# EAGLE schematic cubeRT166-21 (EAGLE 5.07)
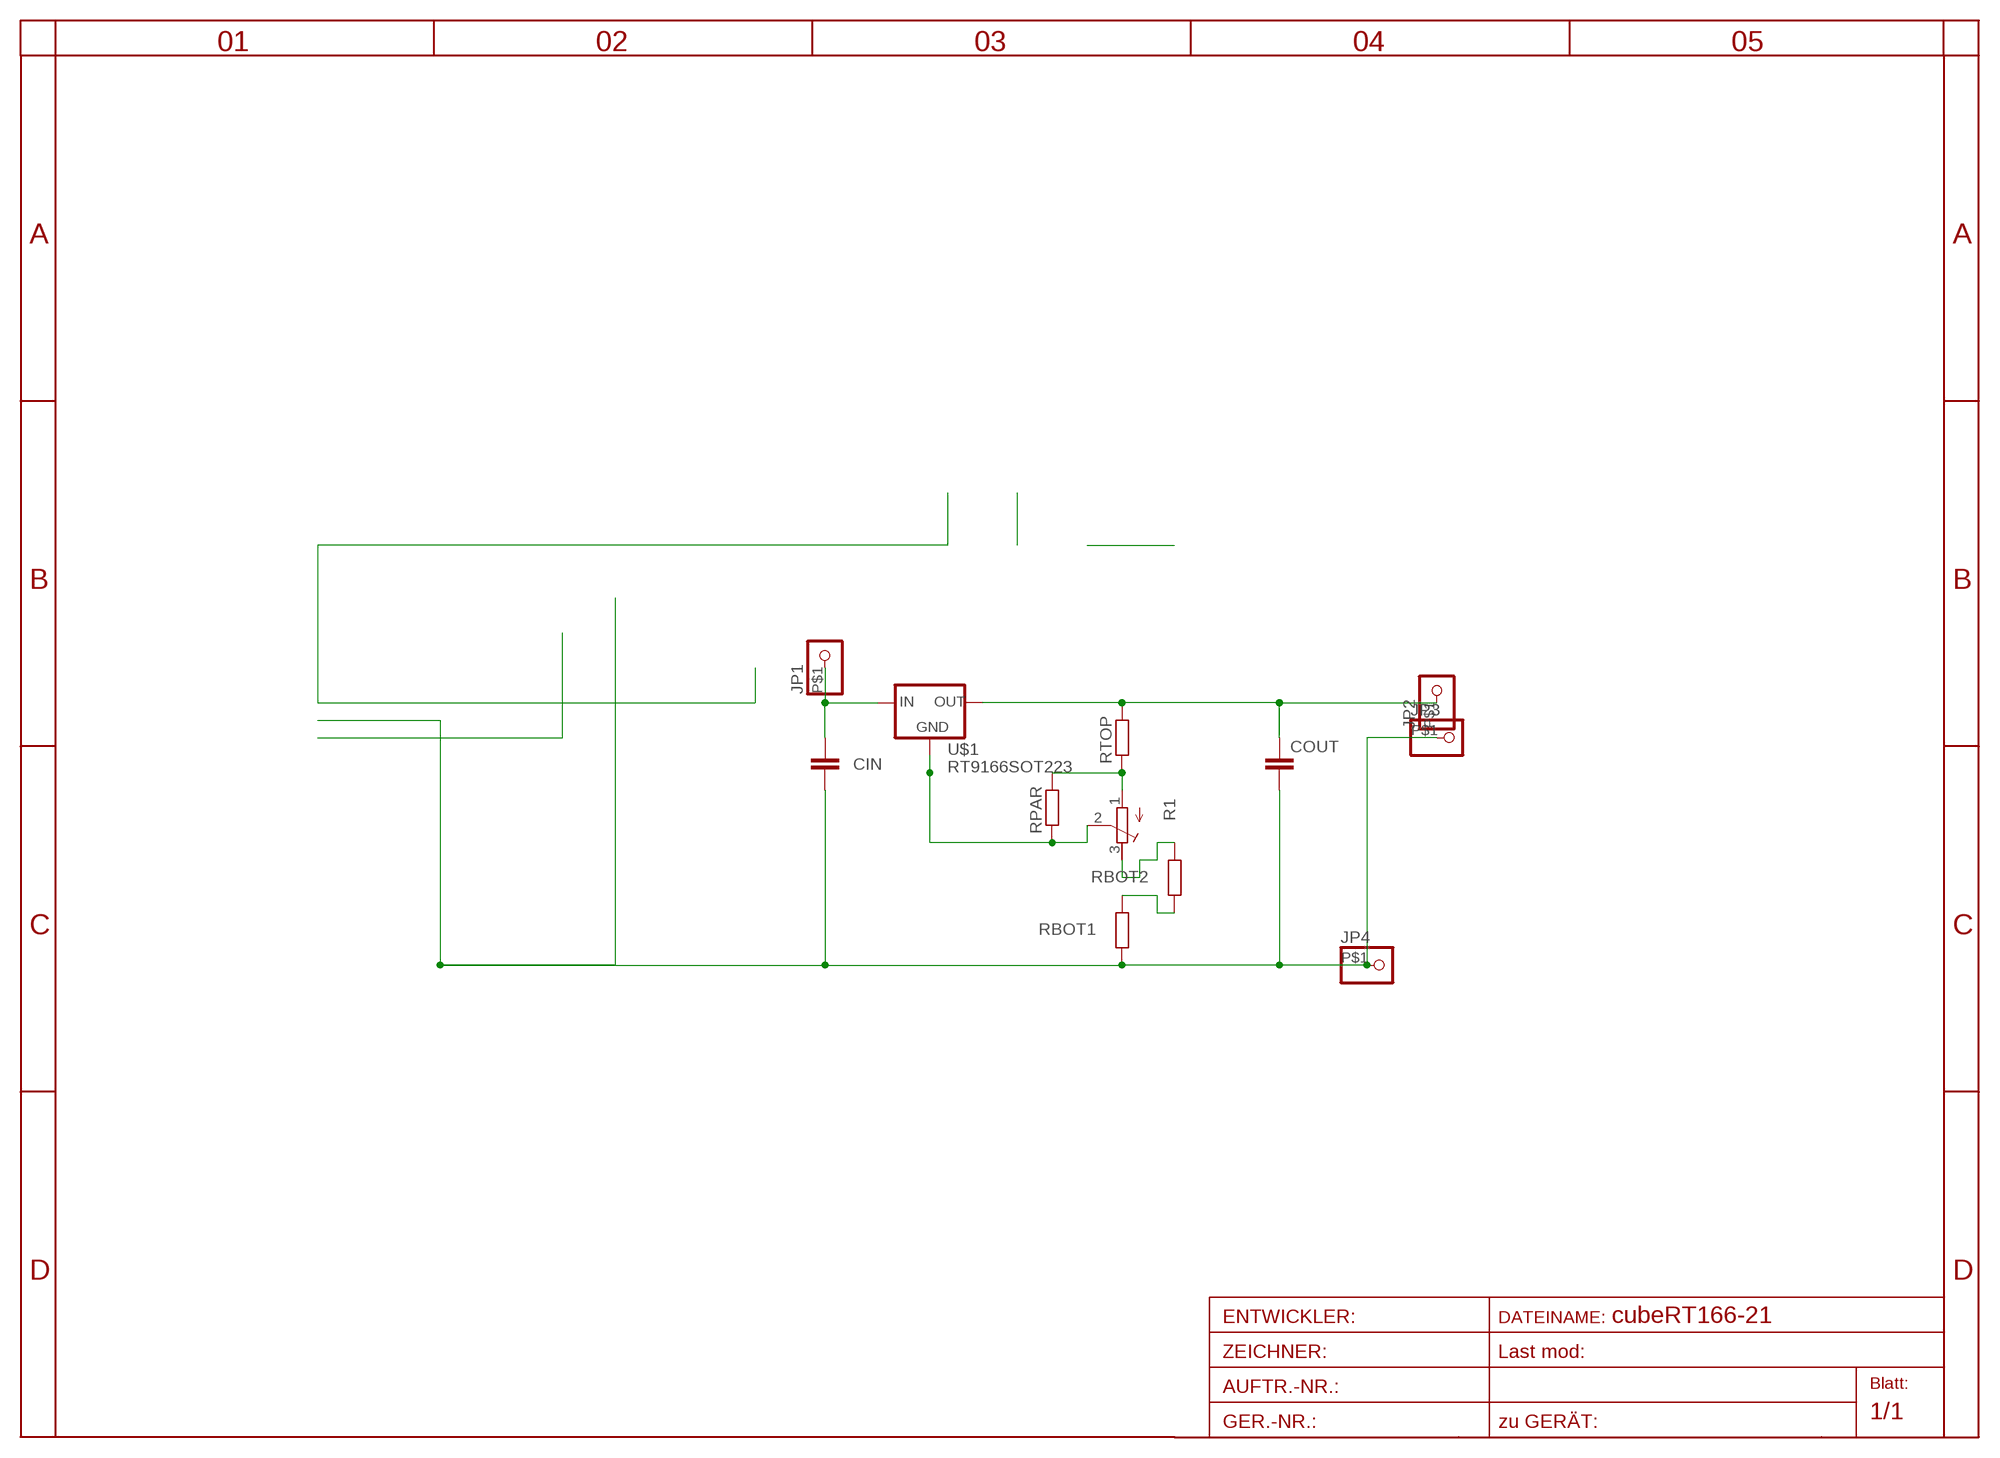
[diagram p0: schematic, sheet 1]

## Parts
CIN  C-EUC1206  [C1206]
COUT  C-EUC1206  [C1206]
JP1  PINHD-1X1SMD50  [1SMD]
JP2  PINHD-1X1SMD50  [1SMD]
JP3  PINHD-1X1SMD50  [1SMD]
JP4  PINHD-1X1SMD50  [1SMD]
R1  R-TRIMM3202  [RTRIM3202]
RBOT1  R-EU_R0805  [R0805]
RBOT2  R-EU_R0805  [R0805]
RPAR  R-EU_R0805  [R0805]
RTOP  R-EU_R0805  [R0805]
U$1  RT9166SOT223  [SOT223]

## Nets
ADJ: R1.2(S) RPAR.1 U$1.2(GND) U$1.4(GND1)
GND: CIN.2 COUT.2 JP3.P$1 JP4.P$1 RBOT1.1
IN: CIN.1 JP1.P$1 U$1.3(IN)
N$2: R1.1(E) RPAR.2 RTOP.1
N$4: R1.3(A) RBOT2.2
N$5: RBOT1.2 RBOT2.1
OUT: COUT.1 JP2.P$1 RTOP.2 U$1.1(OUT)

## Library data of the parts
CIN COUT = rcl:C-EU: CAPACITOR, European symbol
JP1-JP4 = pinhead:PINHD-1X1: PIN HEADER
R1 = rcl:R-TRIMM: Trimm resistor
RBOT1 RBOT2 RPAR RTOP = rcl:R-EU_: RESISTOR, European symbol
U$1 = v-reg:RT9166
